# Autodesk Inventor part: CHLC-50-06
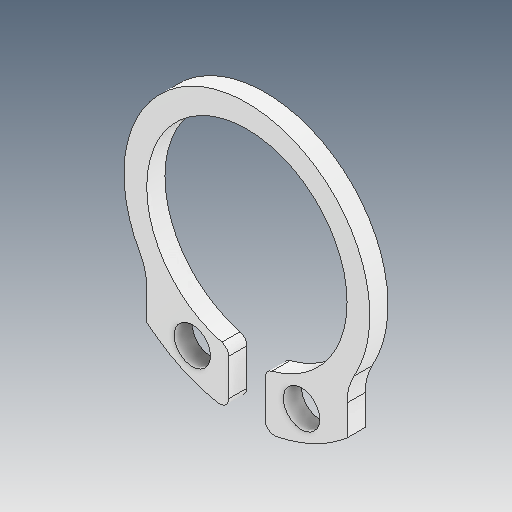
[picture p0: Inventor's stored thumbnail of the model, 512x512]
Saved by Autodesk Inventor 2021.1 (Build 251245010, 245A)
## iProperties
Created: 2021-05
Part Number: CHLC-50-06
Material: Ogólny
Document SubType Name: Modeling
Designer: user
Density: 1 g/cm^3
Appearance: Domyślna
Author: user
Revision Number: ÈÎºÎ
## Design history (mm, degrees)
feature "ÊäÈë1"
node "Bryła1"
